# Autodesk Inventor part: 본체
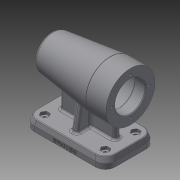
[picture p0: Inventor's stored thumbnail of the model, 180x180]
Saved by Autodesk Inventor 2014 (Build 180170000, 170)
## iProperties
Created: 2017-01
Part Number: 본체
Material: 일반
Document SubType Name: Modeling
Designer: owner
Density: 1 g/cm^3
Appearance: 기본값
Author: owner
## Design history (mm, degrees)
sketch "스케치1"
  geometry: L1 (-56, 0)-(56, 0); L2 (56, 21)-(56, 34); L3 (56, 34)-(28, 34); L4 (28, 34)-(-52.27, 24.144); L5 (56, 21)-(41, 21); L6 (41, 21)-(41, 24); L7 (41, 24)-(-13, 24); L8 (-13, 24)-(-13, 21); L9 (-13, 21)-(-25, 21); L10 (-25, 21)-(-25, 17.5); L11 (-25, 17.5)-(-43, 17.5); L12 (-43, 17.5)-(-43, 16); L13 (-43, 16)-(-47, 16); L14 (-47, 16)-(-47, 10.5); L15 (-47, 10.5)-(-50, 10.5); L16 (-50, 10.5)-(-50, 0); A1 r 80 centre (24, 0) between (-52.27, 24.144) and (-56, 0); 2 further points
  constraints: 32 end point, 9 parallel, 4 perpendicular, 2 horizontal alignment, 2 point on circle, 1 centre point, 1 coincident, 1 collinear, 1 horizontal, 1 midpoint, 1 point on line, 1 vertical alignment
  dimensions: "d0" = 112 distance of L1.start L1.end; "d2" = 68 diameter of L3 L1; "d3" = 42 diameter of L5 L1; "d4" = 48 diameter of L7 L1; "d5" = 42 diameter of L9 L1; "d6" = 35 diameter of L11 L1; "d7" = 32 diameter of L13 L1; "d8" = 21 diameter of L15 L1; "d9" = 28 distance of L2.end L3.end; "d10" = 80 radius of A1; "d11" = 15 distance of L2.start L5.end; "d12" = 54 distance of L6.end L7.end; "d13" = 12 distance of L8.end L9.end; "d14" = 18 distance of L10.end L11.end; "d15" = 4 distance of L12.end L13.end; "d16" = 3 distance of L14.end L15.end; "d17" = 7 deg angle of L4 L3
revolve "회전1" sketch "스케치1" stored, may be unused: angle "d18" = 90 deg
sketch "스케치2"
  geometry: C1 r 34 at (0, 0) reference; 1 further point
  constraints: 1 vertical alignment
  dimensions: "d19" = 26 distance of C1.centre point (0, 26)
hole "구멍1" sketch "스케치2" at (0, 26) diameter "d20" = 3.242; stored, may be unused: countersink angle "d24" = 90 deg, drill point angle "d26" = 118 deg; dims "d21" = 8, "d22" = 4, "d23" = 2, "d25" = 11
fillet "모깎기1" dims "d30" = 3, "d31" = 0.3
chamfer "모따기1" distance "d32" = 1; stored, may be unused: second distance "d33" = 2, angle "d34" = 45 deg
node "작업 평면3"
sketch "스케치5"
  geometry: L1 (56, -35)-(-56, -35); L2 (-56, -35)-(-56, 35); L3 (-56, 35)-(56, 35); L4 (56, 35)-(56, -35); L5 (56, -35)-(-56, 35); L6 (-56, -35)-(56, 35); 1 further point
  constraints: 12 end point, 2 midpoint, 2 parallel, 1 horizontal, 1 perpendicular
  dimensions: "d45" = 112 distance of L2.end L3.end; "d46" = 70 distance of L1.end L2.end
extrude "돌출3" join sketch "스케치5" distance "d47" = 7; taper "d48" = -15 deg
fillet "모깎기2" dims "d49" = 14, "d50" = 1
sketch "스케치6"
  geometry: L1 (42.477, 35)-(-42.477, 35) reference; L2 (-56, 21.477)-(-56, -21.477) reference; L3 (-42.477, -35)-(42.477, -35) reference; L4 (56, -21.477)-(56, 21.477) reference; L5 (56, 35)-(-56, 35); L6 (-56, 35)-(-56, -35); L7 (-56, -35)-(56, -35); L8 (56, -35)-(56, 35); L9 (56, 35)-(-56, -35); L10 (-56, 35)-(56, -35); 5 further points; 4 other entities
  constraints: 12 end point, 2 midpoint, 2 parallel, 1 horizontal, 1 perpendicular, 4 other
  dimensions: "d51" = 112 distance of L6.end L7.end; "d52" = 70 distance of L7.end L5.start
extrude "돌출4" join sketch "스케치6" distance "d53" = 7; taper "d54" = 0 deg
sketch "스케치10"
  geometry: L1 (-47.774, -21)-(-44.887, -16); L2 (-44.887, -16)-(-39.113, -16); L3 (-39.113, -16)-(-36.226, -21); L4 (-36.226, -21)-(-39.113, -26); L5 (-39.113, -26)-(-44.887, -26); L6 (-44.887, -26)-(-47.774, -21); L7 (-56, -21.477)-(-56, 21.477) reference; L8 (42.477, -35)-(-42.477, -35) reference; 6 further points; 1 other entity
  constraints: 12 end point, 1 coincident, 1 horizontal alignment, 14 other
  dimensions: "d115" = 5 distance from line of L5 point (-42, -21); "d123" = 14 distance from line of L7 point (-42, -21); "d124" = 14 distance from line of L8 point (-42, -21)
extrude "돌출5" cut sketch "스케치10" distance "d60" = 4; taper "d61" = 0 deg
fillet "모깎기3" dims "d71" = 3
sketch "스케치12"
  geometry: L1 (-28, -34)-(-56, -34) reference; L2 (50.331, -24.382)-(-28, -34) reference; L3 (-53.357, -60)-(-40.8, -60) reference; L4 (-40.8, -60)-(40.8, -60) reference; L5 (40.8, -60)-(53.357, -60) reference; 1 further point
node "작업 평면4"
sketch "스케치13"
  geometry: L1 (60, 19.8)-(60, -19.8) reference; L2 (60, -32.357)-(60, -19.8) reference; L3 (60, 19.8)-(60, 32.357) reference; L4 (67, -35)-(74, -35) reference; L5 (67, 35)-(74, 35) reference; L6 (60, -4)-(33.764, -4); L7 (33.764, 4)-(60, 4); A1 r 34 centre (0, 0) between (29.118, -17.555) and (29.118, 17.555) reference; 3 further points
  constraints: 4 end point, 4 point on circle, 4 point on line, 1 parallel, 1 perpendicular
  dimensions: "d89" = 4 vertical distance of L6.end point (0, 0); "d90" = 4 vertical distance of point (0, 0) L7.end
extrude "돌출6" join sketch "스케치13" distance "d79" = 10; taper "d80" = 0 deg
sketch "스케치14"
  geometry: L1 (-28, -60)-(-28, -29.118) reference; L2 (50.331, -24.382)-(-28, -34) reference; L3 (40.8, -60)-(53.357, -60) reference; L4 (-40.8, -60)-(40.8, -60) reference; L5 (38, -60)-(38, -25.896); L6 (56, -67)-(56, -74) reference; 2 further points
  constraints: 2 end point, 2 point on line, 1 perpendicular
  dimensions: "d81" = 18 distance from line of L6 L5.start
feature "리브1" sketch "스케치14" dims "d82" = 1, "d83" = 8, "d84" = 0, "d85" = 0, "d86" = 1, "d87" = 1
sketch "스케치15"
  geometry: L1 (19.8, -60)-(-19.8, -60) reference; L2 (19.8, -60)-(32.357, -60) reference; L3 (-32.357, -60)-(-19.8, -60) reference; L4 (4, -60)-(4, -33.764) reference; L5 (-4, -33.764)-(-4, -60) reference; L6 (4, -33.764)-(4, -25.585) reference; L7 (-4, -25.585)-(-4, -33.764) reference; L8 (4, -33.764)-(4, -25.585) reference; L9 (-4, -25.585)-(-4, -33.764) reference; L10 (23, -60)-(15.708, -18.648); L11 (-15.708, -18.648)-(-23, -60); L12 (35, -67)-(35, -74) reference; L13 (-35, -67)-(-35, -74) reference; L14 (4, -60)-(-4, -60) reference; L15 (4, -60)-(4, -33.764) reference; L16 (-4, -33.764)-(-4, -60) reference; L17 (4, -33.764)-(4, -25.585) reference; L18 (4, -60)-(4, -33.764) reference; L19 (4, -25.585)-(4, -60) reference; L20 (-4, -25.585)-(-4, -33.764) reference; L21 (-4, -60)-(-4, -25.585) reference; L22 (-4, -33.764)-(-4, -60) reference; C1 r 22 at (0, 0) reference; C2 r 1.621 at (0, -26) reference; C3 r 1.621 at (26, 0) reference; C4 r 1.621 at (0, 26) reference; C5 r 1.621 at (-26, 0) reference; C6 r 34 at (0, 0) reference; C7 r 24 at (0, 0) reference; C8 r 24 at (0, 0) reference; A1 r 24.382 centre (0, 0) between (15.708, -18.648) and (-15.708, -18.648) reference; A2 r 34 centre (0, 0) between (4, -33.764) and (-4, -33.764) reference; A3 r 25.896 centre (0, 0) between (-4, -25.585) and (4, -25.585) reference; A4 r 34 centre (0, 0) between (-4, -33.764) and (4, -33.764) reference; A5 r 34 centre (0, 0) between (4, -33.764) and (-4, -33.764) reference; 1 further point
  constraints: 4 end point, 2 point on circle, 2 point on line
  dimensions: "d91" = 100 deg angle of L10 L2; "d92" = 100 deg angle of L3 L11; "d93" = 12 distance from line of L12 L10.start; "d94" = 12 distance from line of L13 L11.end
  node "투영된 루프2"
  node "투영된 루프3"
  node "투영된 루프4"
  node "투영된 루프5"
  node "투영된 루프6"
  node "투영된 루프7"
feature "리브2" dims "d95" = 1, "d96" = 8, "d97" = 0, "d98" = 0, "d99" = 1, "d100" = 1
feature "리브3" dims "d101" = 1, "d102" = 8, "d103" = 0, "d104" = 0, "d105" = 1, "d106" = 1
fillet "모깎기4" dims "d107" = 3
sketch "스케치16"
  geometry: L1 (98.477, 7)-(98.477, 0) reference; L2 (84.954, 0)-(98.477, 0) reference; 2 further points
  constraints: 1 other
  dimensions: "d108" = 56 distance from line of L1 point (42.477, 4); "d109" = 4 distance from line of L2 point (42.477, 4)
feature "엠보싱1" sketch "스케치16" dims "d110" = 0.5, "d111" = 0
fillet "모깎기5" dims "d112" = 3
hole "구멍3" sketch "스케치10" diameter "d116" = 5; stored, may be unused: countersink angle "d120" = 90 deg, drill point angle "d122" = 0 deg; dims "d117" = 8, "d118" = 10, "d119" = 4, "d121" = 11
node "솔리드1"
pattern_circular "원형 패턴1" dims angle "d28" = 360 deg
mirror "대칭3"
mirror "대칭4"
other parameters: "d44" = -67, "d74" = -28
